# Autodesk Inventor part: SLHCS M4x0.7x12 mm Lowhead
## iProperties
Author: Chris
Created: 2002-03
Part Number: SLHCS M4x0.7x12 mm Lowhead
Description: SLHCS M4x0.7x12 mm Lowhead
Document SubType Name: Modeling
Designer: Chris
Control State: 0
Master: False
Checked Out: False
Last Check In By: Chris
Last Check In Date: 2002-03-15
PropertySet Name: Design Tracking Control
Shininess: 41.0
Angle Display Precision: 2
Document Length Units: 11269
Document Angle Units: 11283
Document Time Units: 11279
Document Mass Units: 11290
Document Length Units Precision: 3
Document Angle Units Precision: 2
Compacted: True
PropertySet Name: _Private Model Information
Density: 0.0
Volumn: 0.0
Area: 0.0
PropertySet Name: Model Information
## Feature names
1. Extrusion1
2. Extrusion2
3. Extrusion3
4. Fillet1
5. Chamfer1
